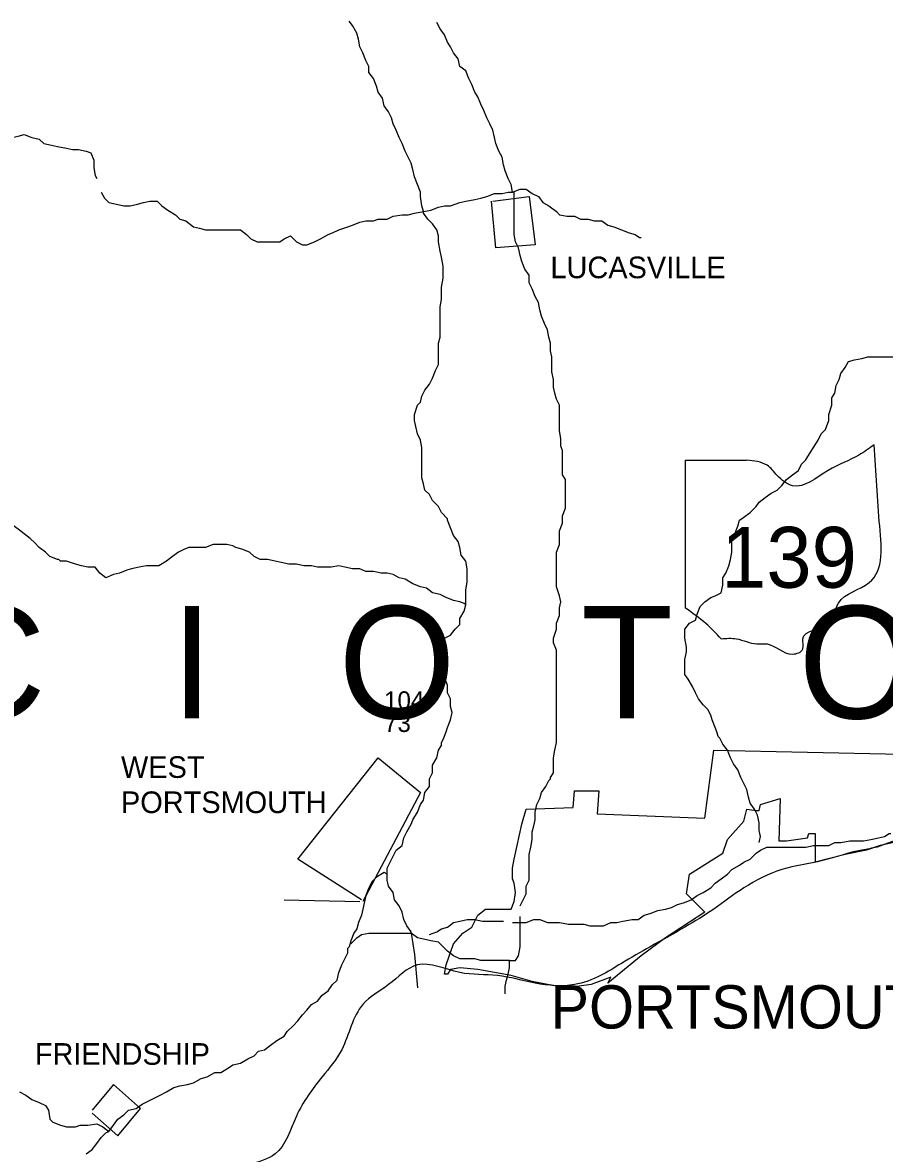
# Model space of a CAD drawing. Extents: x 0 to 40.2, y 0 to 22.
# Drawn here: x 5.589 to 6.366, y 16.218 to 17.238 of the extents above; entities that cross this region are included whole.
import ezdxf

# ---------------------------------------------------------------- set-up
doc = ezdxf.new("R2010")
doc.units = 0
doc.layers.add('Default', color=7, linetype='Continuous')
doc.layers.add('TR_Turning_Path1', color=7, linetype='Continuous')

msp = doc.modelspace()

# ---------------------------------------------------------------- linework, layer by layer
at = {"layer": 'Default'}
msp.add_line((5.8248, 16.4467), (5.893, 16.4454), dxfattribs=at)
for points in [[(5.9448, 17.0916), (5.9421, 17.0984), (5.9407, 17.1052), (5.9393, 17.1107), (5.9366, 17.1162), (5.9339, 17.1216), (5.9312, 17.1284), (5.9284, 17.1339), (5.9257, 17.1407), (5.923, 17.1462), (5.9216, 17.1516), (5.9189, 17.1571), (5.9148, 17.1625), (5.9134, 17.1693), (5.9094, 17.1748), (5.908, 17.1802), (5.9053, 17.1871), (5.9012, 17.1925), (5.9012, 17.198), (5.8984, 17.2034), (5.8957, 17.2102), (5.893, 17.2157), (5.8916, 17.2225), (5.8903, 17.228), (5.8862, 17.2348), (5.8834, 17.2389)], [(6.0307, 17.0848), (6.0293, 17.0916), (6.0266, 17.0971), (6.0239, 17.1039), (6.0225, 17.1093), (6.0212, 17.1162), (6.0184, 17.1216), (6.0157, 17.1284), (6.0143, 17.1339), (6.013, 17.1407), (6.0102, 17.1462), (6.0075, 17.1516), (6.0048, 17.1584), (6.0021, 17.1639), (5.9993, 17.1707), (5.9966, 17.1748), (5.9939, 17.1816), (5.9912, 17.1871), (5.9884, 17.1939), (5.983, 17.198), (5.9816, 17.2048), (5.9775, 17.2102), (5.9748, 17.2157), (5.9721, 17.2198), (5.9693, 17.2266), (5.9653, 17.232), (5.9625, 17.2375)], [(5.5603, 17.1325), (5.5658, 17.1325), (5.5726, 17.1325), (5.5794, 17.1339), (5.5849, 17.1352), (5.5903, 17.1366), (5.5971, 17.1339), (5.6039, 17.1325), (5.608, 17.1284), (5.6149, 17.1271), (5.6203, 17.1257), (5.6285, 17.1243), (5.6339, 17.123), (5.6394, 17.123), (5.6462, 17.1216), (5.6503, 17.1202), (5.653, 17.1134), (5.653, 17.1066), (5.6544, 17.0998), (5.6558, 17.0971), (5.6558, 17.0971)], [(5.6598, 17.0848), (5.6626, 17.0793), (5.6667, 17.0753), (5.6735, 17.0739), (5.6803, 17.0725), (5.6858, 17.0725), (5.6926, 17.0739), (5.698, 17.0753), (5.7035, 17.0766), (5.7103, 17.0766), (5.7144, 17.0725), (5.7198, 17.0684), (5.7267, 17.0643), (5.7307, 17.0603), (5.7362, 17.0589), (5.743, 17.0534), (5.7485, 17.0521), (5.7539, 17.0507), (5.7607, 17.0507), (5.7676, 17.0507), (5.773, 17.0507), (5.7785, 17.0507), (5.7853, 17.0507), (5.7907, 17.0466), (5.7948, 17.0425), (5.8003, 17.0398), (5.8071, 17.0398)], [(5.9503, 17.0671), (5.9489, 17.0725), (5.9475, 17.0807), (5.9475, 17.0848), (5.9448, 17.0916), (5.9448, 17.0916)], [(5.9503, 17.0671), (5.9571, 17.0684), (5.9639, 17.0712), (5.9693, 17.0725), (5.9748, 17.0725), (5.983, 17.0753), (5.9884, 17.0766), (5.9966, 17.078), (6.0021, 17.0793), (6.0075, 17.0807), (6.0143, 17.0834), (6.0212, 17.0834), (6.0266, 17.0848), (6.0307, 17.0848)], [(6.0307, 17.0848), (6.0375, 17.0875), (6.043, 17.0875), (6.0484, 17.0834), (6.0539, 17.0807), (6.058, 17.0753), (6.0634, 17.0725), (6.0702, 17.0671), (6.073, 17.0643), (6.0798, 17.063), (6.0866, 17.063), (6.092, 17.0603), (6.0989, 17.0603), (6.1043, 17.0589), (6.1111, 17.0589), (6.1166, 17.0548), (6.122, 17.0534), (6.1289, 17.0507), (6.1357, 17.048), (6.1411, 17.0466), (6.1452, 17.0439), (6.1466, 17.0439)], [(6.073, 16.8857), (6.073, 16.8926), (6.0702, 16.898), (6.0689, 16.9035), (6.0675, 16.9089), (6.0675, 16.9157), (6.0661, 16.9226), (6.0661, 16.9294), (6.0661, 16.9362), (6.0648, 16.9416), (6.0648, 16.9485), (6.0634, 16.9539), (6.0621, 16.9607), (6.0593, 16.9662), (6.0566, 16.973), (6.0552, 16.9785), (6.0539, 16.9853), (6.0511, 16.9907), (6.0484, 16.9975), (6.0457, 17.003), (6.0457, 17.0098), (6.0416, 17.0153), (6.0389, 17.0221), (6.0375, 17.0275), (6.0361, 17.0344), (6.0334, 17.0398), (6.0321, 17.0466), (6.0321, 17.0507), (6.0321, 17.0589), (6.0321, 17.0643), (6.0321, 17.0712), (6.0321, 17.078), (6.0321, 17.0834), (6.0321, 17.0848), (6.0307, 17.0848)], [(6.013, 17.0766), (6.0457, 17.0807), (6.0511, 17.0371), (6.0157, 17.0344), (6.0116, 17.0766)], [(5.8071, 17.0398), (5.8125, 17.0398), (5.8207, 17.0398), (5.8248, 17.0425), (5.8303, 17.0453), (5.8357, 17.0398), (5.8412, 17.0371), (5.8453, 17.0371), (5.8521, 17.0398), (5.8575, 17.0425), (5.8644, 17.0466), (5.8684, 17.048), (5.8739, 17.0507), (5.8821, 17.0534), (5.8862, 17.0548), (5.893, 17.0575), (5.8984, 17.0589), (5.9053, 17.0589), (5.9094, 17.0603), (5.9175, 17.0603), (5.923, 17.063), (5.9312, 17.0643), (5.9366, 17.0643), (5.9421, 17.0657), (5.9503, 17.0671), (5.9503, 17.0671)], [(5.9475, 16.8953), (5.9489, 16.9007), (5.9516, 16.9062), (5.9557, 16.9116), (5.9584, 16.9171), (5.9612, 16.9239), (5.9639, 16.9294), (5.9639, 16.9362), (5.9639, 16.9416), (5.9639, 16.9485), (5.9653, 16.9539), (5.9653, 16.9607), (5.9653, 16.9675), (5.9653, 16.9744), (5.9653, 16.9812), (5.9666, 16.988), (5.9666, 16.9934), (5.9666, 16.9989), (5.968, 17.0071), (5.968, 17.0139), (5.968, 17.018), (5.9666, 17.0262), (5.9653, 17.0316), (5.9639, 17.0398), (5.9639, 17.0453), (5.9625, 17.0507), (5.9584, 17.0562), (5.9543, 17.0603), (5.9503, 17.0657), (5.9503, 17.0671), (5.9503, 17.0671)], [(6.3157, 16.8789), (6.3157, 16.8844), (6.3184, 16.8926), (6.3184, 16.8994), (6.3211, 16.9035), (6.3225, 16.9103), (6.3252, 16.9157), (6.3266, 16.9212), (6.3306, 16.9266), (6.3334, 16.9321), (6.3388, 16.9335), (6.3456, 16.9348), (6.3511, 16.9362), (6.3579, 16.9362), (6.3647, 16.9362), (6.3702, 16.9362), (6.3756, 16.9362), (6.3825, 16.9335), (6.3865, 16.9307), (6.392, 16.9294), (6.392, 16.9294)], [(5.9721, 16.7903), (5.9666, 16.7958), (5.9639, 16.8012), (5.9584, 16.8067), (5.9557, 16.8121), (5.9516, 16.8162), (5.9503, 16.8217), (5.9489, 16.8271), (5.9489, 16.8353), (5.9489, 16.8421), (5.9489, 16.8476), (5.9489, 16.8544), (5.9475, 16.8612), (5.9448, 16.8667), (5.9434, 16.8735), (5.9421, 16.8789), (5.9421, 16.8844), (5.9448, 16.8926), (5.9475, 16.8953)], [(6.0702, 16.7289), (6.0702, 16.7358), (6.0702, 16.7412), (6.0702, 16.748), (6.0702, 16.7535), (6.0702, 16.7603), (6.073, 16.7671), (6.073, 16.7726), (6.073, 16.7794), (6.0757, 16.7862), (6.0757, 16.793), (6.0784, 16.7998), (6.0784, 16.8053), (6.0784, 16.8108), (6.0784, 16.8189), (6.0784, 16.8257), (6.0757, 16.8298), (6.0757, 16.838), (6.0757, 16.8435), (6.0757, 16.8517), (6.0743, 16.8557), (6.0743, 16.8626), (6.073, 16.8694), (6.073, 16.8762), (6.073, 16.883), (6.073, 16.8844), (6.073, 16.8857)], [(6.2311, 16.7767), (6.2338, 16.7835), (6.2352, 16.7889), (6.2393, 16.7917), (6.2448, 16.7958), (6.2502, 16.8012), (6.2529, 16.8053), (6.2584, 16.8094), (6.2638, 16.8135), (6.2693, 16.8162), (6.2734, 16.8203), (6.2775, 16.8257), (6.2829, 16.8298), (6.2884, 16.8339), (6.2911, 16.8394), (6.2952, 16.8435), (6.2993, 16.8503), (6.302, 16.8544), (6.3061, 16.8612), (6.3088, 16.8667), (6.3129, 16.8707), (6.3157, 16.8789), (6.3157, 16.8789)], [(6.3613, 16.7879), (6.3567, 16.8569)], [(6.1865, 16.7097), (6.1865, 16.8431), (6.2417, 16.8431)], [(5.623, 16.7521), (5.6217, 16.7535), (5.6203, 16.7535), (5.6135, 16.7562), (5.6094, 16.7603), (5.6039, 16.7644), (5.5999, 16.7685), (5.5958, 16.7726), (5.5903, 16.7767), (5.5849, 16.7808), (5.5794, 16.7848), (5.574, 16.7889), (5.5699, 16.7903), (5.563, 16.7944), (5.5576, 16.7958), (5.5521, 16.7985), (5.5467, 16.8026)], [(5.9884, 16.7126), (5.9884, 16.7194), (5.9884, 16.7262), (5.9898, 16.733), (5.9898, 16.7399), (5.9898, 16.7453), (5.9884, 16.7521), (5.9843, 16.7576), (5.983, 16.7644), (5.9816, 16.7698), (5.9775, 16.7753), (5.9748, 16.7821), (5.9721, 16.7889), (5.9721, 16.7889), (5.9721, 16.7903)], [(5.7812, 16.7644), (5.7812, 16.7644), (5.7785, 16.7658), (5.773, 16.7671), (5.7662, 16.7671), (5.7607, 16.7671), (5.7539, 16.7644), (5.7457, 16.7644), (5.7389, 16.7644), (5.7348, 16.763), (5.7294, 16.7603), (5.7239, 16.7562), (5.7185, 16.7521), (5.7117, 16.748), (5.7062, 16.748), (5.7007, 16.748), (5.6939, 16.7467), (5.6871, 16.7453), (5.683, 16.7439), (5.6762, 16.7412), (5.6708, 16.7399), (5.6639, 16.7371), (5.6585, 16.7412), (5.6544, 16.7467), (5.6476, 16.7467), (5.6421, 16.748), (5.6367, 16.7494), (5.6285, 16.7521), (5.623, 16.7521)], [(6.1861, 16.6908), (6.1902, 16.6962), (6.1957, 16.699), (6.197, 16.7044), (6.1998, 16.7112), (6.2039, 16.7153), (6.2093, 16.7194), (6.2134, 16.7208), (6.2188, 16.7235), (6.2202, 16.7303), (6.2202, 16.7371), (6.2229, 16.7412), (6.2257, 16.748), (6.227, 16.7535), (6.2284, 16.7603), (6.2284, 16.7644), (6.2284, 16.7726), (6.2311, 16.7753), (6.2311, 16.7767)], [(5.9884, 16.7126), (5.9871, 16.7139), (5.983, 16.7153), (5.9775, 16.7167), (5.9707, 16.7194), (5.9653, 16.7221), (5.9584, 16.7235), (5.953, 16.7276), (5.9475, 16.7289), (5.9407, 16.7317), (5.9339, 16.7358), (5.9284, 16.7371), (5.923, 16.7399), (5.9175, 16.7412), (5.9121, 16.7412), (5.9053, 16.7426), (5.8984, 16.7426), (5.893, 16.7453), (5.8862, 16.7453), (5.8794, 16.7467), (5.8739, 16.748), (5.8671, 16.7467), (5.8603, 16.7467), (5.8548, 16.7467), (5.8494, 16.748), (5.8425, 16.748), (5.8357, 16.7494), (5.8289, 16.7494), (5.8221, 16.7508), (5.8166, 16.7521), (5.8098, 16.7535), (5.803, 16.7535), (5.7976, 16.7562), (5.7935, 16.7603), (5.7866, 16.763), (5.7812, 16.7644)], [(6.0648, 16.5572), (6.0675, 16.5612), (6.0675, 16.5681), (6.0675, 16.5749), (6.0689, 16.5817), (6.0702, 16.5885), (6.0702, 16.594), (6.0702, 16.6008), (6.0702, 16.6062), (6.0702, 16.6131), (6.0702, 16.6199), (6.0702, 16.6253), (6.0702, 16.6335), (6.0702, 16.639), (6.0702, 16.6458), (6.0702, 16.6499), (6.0702, 16.658), (6.0702, 16.6635), (6.0702, 16.6717), (6.0675, 16.6785), (6.0675, 16.6826), (6.0702, 16.6908), (6.0702, 16.6962), (6.073, 16.703), (6.073, 16.7099), (6.0743, 16.7153), (6.073, 16.7208), (6.0702, 16.7289)], [(5.9666, 16.5858), (5.9666, 16.5885), (5.968, 16.5912), (5.9707, 16.5981), (5.9721, 16.6021), (5.9748, 16.609), (5.9762, 16.6158), (5.9748, 16.6212), (5.9748, 16.6281), (5.9721, 16.6335), (5.9721, 16.6403), (5.9693, 16.6471), (5.968, 16.6526), (5.9666, 16.658), (5.9653, 16.6649), (5.9653, 16.6717), (5.9653, 16.6785), (5.9693, 16.6826), (5.9748, 16.6853), (5.9789, 16.6908), (5.983, 16.6949), (5.983, 16.7003), (5.9871, 16.7071), (5.9884, 16.7126)], [(5.9666, 16.5858), (5.9666, 16.5885), (5.968, 16.5912), (5.9707, 16.5981), (5.9721, 16.6021), (5.9748, 16.609), (5.9762, 16.6158), (5.9748, 16.6212), (5.9748, 16.6281), (5.9721, 16.6335), (5.9721, 16.6403), (5.9693, 16.6471), (5.968, 16.6526), (5.9666, 16.658), (5.9653, 16.6649), (5.9653, 16.6717), (5.9653, 16.6785), (5.9693, 16.6826), (5.9748, 16.6853), (5.9789, 16.6908), (5.983, 16.6949), (5.983, 16.7003), (5.9871, 16.7071), (5.9884, 16.7126)], [(6.2148, 16.5981), (6.2134, 16.6021), (6.2107, 16.609), (6.2093, 16.6131), (6.2066, 16.6185), (6.2025, 16.6226), (6.1984, 16.6281), (6.1957, 16.6335), (6.1929, 16.639), (6.1889, 16.6458), (6.1861, 16.6499), (6.1861, 16.6567), (6.1861, 16.6635), (6.1875, 16.6703), (6.1875, 16.6744), (6.1861, 16.6826), (6.1861, 16.688), (6.1861, 16.6908)], [(6.2529, 16.4985), (6.2543, 16.504), (6.2529, 16.5094), (6.2529, 16.5163), (6.2516, 16.5231), (6.2488, 16.5285), (6.2448, 16.534), (6.2434, 16.5394), (6.242, 16.5462), (6.2393, 16.5517), (6.2366, 16.5572), (6.2338, 16.564), (6.2298, 16.5694), (6.227, 16.5749), (6.2243, 16.5817), (6.2202, 16.5871), (6.2175, 16.5926), (6.2161, 16.594), (6.2148, 16.5981)], [(5.9175, 16.4699), (5.9175, 16.4713), (5.9175, 16.4753), (5.9203, 16.4808), (5.923, 16.4863), (5.9257, 16.4917), (5.9312, 16.4958), (5.9325, 16.5026), (5.9353, 16.5081), (5.9393, 16.5149), (5.9407, 16.519), (5.9448, 16.5258), (5.9475, 16.5326), (5.9503, 16.5367), (5.9516, 16.5435), (5.9557, 16.549), (5.9557, 16.5558), (5.9584, 16.5612), (5.9584, 16.5681), (5.9625, 16.5749), (5.9639, 16.5817), (5.9666, 16.5858)], [(5.9175, 16.4699), (5.9175, 16.4713), (5.9175, 16.4753), (5.9203, 16.4808), (5.923, 16.4863), (5.9257, 16.4917), (5.9312, 16.4958), (5.9325, 16.5026), (5.9353, 16.5081), (5.9393, 16.5149), (5.9407, 16.519), (5.9448, 16.5258), (5.9475, 16.5326), (5.9503, 16.5367), (5.9516, 16.5435), (5.9557, 16.549), (5.9557, 16.5558), (5.9584, 16.5612), (5.9584, 16.5681), (5.9625, 16.5749), (5.9639, 16.5817), (5.9666, 16.5858)], [(5.8944, 16.4467), (5.8371, 16.4835), (5.9094, 16.5749), (5.9475, 16.5435), (5.8957, 16.4454)], [(5.9707, 16.3881), (5.9775, 16.4072), (5.9857, 16.4167), (5.9939, 16.4222), (5.9993, 16.4331), (6.0062, 16.4385), (6.0293, 16.4385), (6.0321, 16.4454), (6.0334, 16.4535), (6.0321, 16.4617), (6.0307, 16.4658), (6.0307, 16.4753), (6.0321, 16.4835), (6.0348, 16.4958), (6.0389, 16.5149), (6.043, 16.5285), (6.0852, 16.5299), (6.0866, 16.5449), (6.1084, 16.5449), (6.107, 16.5244), (6.2039, 16.5203), (6.212, 16.5817), (6.4656, 16.5762)], [(6.0457, 16.4685), (6.0457, 16.4753), (6.0457, 16.4822), (6.0457, 16.4876), (6.0471, 16.4944), (6.0484, 16.5013), (6.0484, 16.5081), (6.0498, 16.5135), (6.0511, 16.519), (6.0511, 16.5258), (6.0525, 16.5326), (6.0552, 16.5381), (6.0566, 16.5435), (6.0607, 16.549), (6.0634, 16.5544), (6.0648, 16.5558), (6.0648, 16.5572)], [(6.2039, 16.4358), (6.1875, 16.4522), (6.1902, 16.4699), (6.2202, 16.489), (6.2243, 16.5013), (6.2393, 16.5176), (6.242, 16.5285), (6.2502, 16.5272), (6.2529, 16.5272), (6.2543, 16.5326), (6.272, 16.5381), (6.2707, 16.4999), (6.2775, 16.4999), (6.2966, 16.5026), (6.2979, 16.5067), (6.3034, 16.5067), (6.3034, 16.4808)], [(6.2829, 16.4944), (6.2884, 16.4944), (6.2952, 16.4944), (6.302, 16.4958), (6.3088, 16.4958), (6.3157, 16.4958), (6.3211, 16.4985), (6.3266, 16.4985), (6.3347, 16.4999), (6.3402, 16.4999), (6.347, 16.4999), (6.3538, 16.5013), (6.3606, 16.5026), (6.3661, 16.504), (6.3702, 16.5067), (6.3716, 16.5067)], [(6.3934, 16.5026), (6.362, 16.4958), (6.3497, 16.4917), (6.3306, 16.4876), (6.3034, 16.4808)], [(6.1616, 16.4372), (6.1684, 16.4385), (6.1739, 16.4399), (6.1793, 16.4426), (6.1848, 16.444), (6.1916, 16.4467), (6.197, 16.4508), (6.2025, 16.4535), (6.2093, 16.4576), (6.2134, 16.4617), (6.2188, 16.4658), (6.2243, 16.4699), (6.2284, 16.474), (6.2352, 16.4781), (6.2393, 16.4808), (6.2448, 16.4835), (6.2502, 16.489), (6.2543, 16.4917), (6.2598, 16.4944), (6.2598, 16.4944)], [(6.2598, 16.4944), (6.2666, 16.4944), (6.2734, 16.4944), (6.2802, 16.4944), (6.2829, 16.4944)], [(5.9175, 16.4699), (5.9175, 16.4699), (5.9148, 16.4713), (5.908, 16.4672), (5.9039, 16.4631), (5.9012, 16.4576), (5.8984, 16.4508), (5.8971, 16.4454), (5.8957, 16.4385), (5.8944, 16.4331), (5.8916, 16.4263), (5.8903, 16.4208)], [(5.9393, 16.4167), (5.9393, 16.4181), (5.9353, 16.4235), (5.9325, 16.429), (5.9312, 16.4358), (5.9284, 16.4413), (5.9243, 16.4467), (5.923, 16.4535), (5.9189, 16.459), (5.9175, 16.4644), (5.9175, 16.4699)], [(5.9393, 16.4167), (5.9393, 16.4181), (5.9353, 16.4235), (5.9325, 16.429), (5.9312, 16.4358), (5.9284, 16.4413), (5.9243, 16.4467), (5.923, 16.4535), (5.9189, 16.459), (5.9175, 16.4644), (5.9175, 16.4699)], [(6.0375, 16.4413), (6.0402, 16.4467), (6.043, 16.4522), (6.043, 16.459), (6.0457, 16.4644), (6.0457, 16.4685)], [(6.2039, 16.4358), (6.1684, 16.4126), (6.1466, 16.3963), (6.1166, 16.3717), (6.1193, 16.3772), (6.1016, 16.3704), (6.0798, 16.3676), (6.0621, 16.3704), (6.0484, 16.3731), (6.0293, 16.3785), (5.9993, 16.384), (5.983, 16.3854), (5.9748, 16.384), (5.9721, 16.3799)], [(6.0375, 16.4263), (6.0375, 16.4317)], [(6.1248, 16.4263), (6.1302, 16.4276), (6.1384, 16.429), (6.1439, 16.429), (6.1493, 16.4331), (6.1548, 16.4344), (6.1616, 16.4372)], [(5.8903, 16.4208), (5.8875, 16.4167), (5.8848, 16.4099), (5.8834, 16.4045)], [(5.9557, 16.4154), (5.9625, 16.4181), (5.9666, 16.4208), (5.9721, 16.4222), (5.9775, 16.4263), (5.983, 16.4276), (5.9898, 16.429), (5.9966, 16.429), (6.0034, 16.4276), (6.0089, 16.4276), (6.0157, 16.4276), (6.0212, 16.4276), (6.0225, 16.4276)], [(6.028, 16.3922), (6.0334, 16.3922), (6.0361, 16.3963), (6.0375, 16.4045), (6.0375, 16.4099), (6.0375, 16.4167), (6.0375, 16.4222), (6.0375, 16.4263)], [(6.0307, 16.4263), (6.0375, 16.4263), (6.0375, 16.4263)], [(6.0375, 16.4263), (6.043, 16.4263), (6.0498, 16.429), (6.0552, 16.429), (6.0621, 16.4263), (6.0675, 16.4263), (6.073, 16.4263), (6.0811, 16.4249), (6.0866, 16.4249), (6.0948, 16.4249), (6.1002, 16.4235), (6.107, 16.4235), (6.1125, 16.4235), (6.1193, 16.4263), (6.122, 16.4263), (6.1248, 16.4263)], [(5.8848, 16.4072), (5.8903, 16.4126), (5.8944, 16.4154), (5.9012, 16.4167), (5.908, 16.4167), (5.9148, 16.4167), (5.9189, 16.4167), (5.9257, 16.4167), (5.9325, 16.4167), (5.9393, 16.4167), (5.9393, 16.4167)], [(6.028, 16.3922), (6.0266, 16.3922), (6.0225, 16.3922), (6.0157, 16.3922), (6.0089, 16.3922), (6.0021, 16.3922), (5.9966, 16.3935), (5.9898, 16.3935), (5.983, 16.3935), (5.9775, 16.3963), (5.9721, 16.4004), (5.968, 16.4045), (5.9639, 16.4085), (5.9571, 16.4099), (5.9503, 16.4113), (5.9448, 16.4126), (5.9393, 16.4167)], [(6.028, 16.3922), (6.0266, 16.3922), (6.0225, 16.3922), (6.0157, 16.3922), (6.0089, 16.3922), (6.0021, 16.3922), (5.9966, 16.3935), (5.9898, 16.3935), (5.983, 16.3935), (5.9775, 16.3963), (5.9721, 16.4004), (5.968, 16.4045), (5.9639, 16.4085), (5.9571, 16.4099), (5.9503, 16.4113), (5.9448, 16.4126), (5.9393, 16.4167)], [(5.9393, 16.4167), (5.9421, 16.3976), (5.9448, 16.3676)], [(5.7785, 16.2981), (5.7853, 16.2995), (5.7921, 16.3036), (5.7976, 16.3063), (5.8016, 16.3104), (5.8071, 16.3117), (5.8125, 16.3158), (5.818, 16.3199), (5.8248, 16.324), (5.8275, 16.3281), (5.833, 16.3336), (5.8371, 16.3376), (5.8412, 16.3431), (5.8453, 16.3472), (5.8494, 16.3526), (5.8548, 16.3554), (5.8589, 16.3608), (5.8644, 16.3649), (5.8684, 16.3704), (5.8725, 16.3745), (5.8739, 16.3813), (5.8766, 16.3881), (5.8794, 16.3935), (5.8821, 16.399), (5.8821, 16.4031), (5.8834, 16.4045)], [(6.0266, 16.3799), (6.028, 16.3854), (6.028, 16.3922)], [(5.9721, 16.3799), (5.9693, 16.3799), (5.9707, 16.3881)], [(6.0239, 16.3622), (6.0239, 16.369), (6.0252, 16.3745), (6.0266, 16.3799), (6.0266, 16.3799)], [(5.6667, 16.2381), (5.6708, 16.2436), (5.6748, 16.249), (5.6803, 16.2531), (5.6844, 16.2572), (5.6912, 16.2586), (5.6967, 16.2627), (5.7021, 16.2654), (5.7076, 16.2681), (5.713, 16.2708), (5.7185, 16.2736), (5.7253, 16.2777), (5.7307, 16.279), (5.7376, 16.2804), (5.743, 16.2817), (5.7498, 16.2858), (5.7553, 16.2872), (5.7621, 16.2913), (5.7676, 16.2913), (5.7744, 16.2954), (5.7785, 16.2981), (5.7785, 16.2981)], [(5.6517, 16.2545), (5.6748, 16.234), (5.6953, 16.2586), (5.6708, 16.2804), (5.6517, 16.2572)], [(5.5862, 16.2736), (5.5917, 16.2708), (5.5971, 16.2667), (5.6039, 16.264), (5.6094, 16.2613), (5.6121, 16.2572), (5.6135, 16.249), (5.6162, 16.2463), (5.623, 16.2436), (5.6285, 16.2422), (5.6367, 16.2422), (5.6408, 16.2436), (5.6476, 16.2436), (5.6558, 16.2449), (5.6612, 16.2422), (5.6667, 16.2381)], [(5.6462, 16.2177), (5.6517, 16.2218), (5.6558, 16.2272), (5.6598, 16.2327), (5.6639, 16.2368), (5.6667, 16.2381), (5.6667, 16.2381)]]:
    msp.add_lwpolyline(points, dxfattribs=at)
for points in [[(6.3567, 16.8569), (6.3429, 16.8477), (6.3153, 16.8339), (6.2831, 16.8201), (6.2693, 16.8293), (6.2601, 16.8385), (6.2417, 16.8431)], [(6.2187, 16.6821), (6.2325, 16.6821), (6.2509, 16.6775), (6.2601, 16.6775), (6.2831, 16.6683), (6.2923, 16.6729), (6.2923, 16.6821), (6.3153, 16.6959), (6.3245, 16.7143), (6.3521, 16.7327), (6.3613, 16.7879)], [(6.2187, 16.6821), (6.2049, 16.6959), (6.1865, 16.7097)], [(6.6647, 15.66), (6.6347, 15.6791), (6.6101, 15.6982), (6.5788, 15.7227), (6.5583, 15.7596), (6.5447, 15.795), (6.5324, 15.8264), (6.5229, 15.8727), (6.5174, 15.9123), (6.5174, 15.9545), (6.5174, 15.9927), (6.5147, 16.0445), (6.5011, 16.0854), (6.4902, 16.1195), (6.4738, 16.1454), (6.4574, 16.1645), (6.4493, 16.1918), (6.4493, 16.234), (6.4629, 16.2695), (6.4724, 16.3117), (6.4724, 16.3554), (6.4656, 16.3976), (6.4629, 16.4385), (6.4465, 16.4685), (6.4288, 16.4849), (6.4015, 16.4999), (6.3852, 16.5026), (6.3593, 16.4944), (6.3456, 16.4917), (6.3102, 16.4822), (6.2734, 16.474), (6.2393, 16.4576), (6.212, 16.4385), (6.1861, 16.4222), (6.1548, 16.4045), (6.1289, 16.3895), (6.1098, 16.3785), (6.0866, 16.3704), (6.0511, 16.3717), (6.0171, 16.3785), (5.983, 16.3813), (5.9448, 16.3881), (5.9189, 16.3704), (5.8957, 16.3526), (5.8766, 16.3117), (5.8589, 16.2872), (5.8357, 16.2517), (5.8166, 16.2177), (5.7935, 16.2081), (5.7539, 16.1918), (5.7212, 16.1754), (5.6803, 16.1631), (5.653, 16.1481), (5.6162, 16.1318), (5.5944, 16.1018), (5.5821, 16.0772), (5.5685, 16.0418), (5.559, 16.0077), (5.5562, 15.9668), (5.5249, 15.9382), (5.4908, 15.9123), (5.4431, 15.8891), (5.3926, 15.8891), (5.3517, 15.8809), (5.3067, 15.8809), (5.2631, 15.8864), (5.2222, 15.9054), (5.1963, 15.9232), (5.1622, 15.93), (5.1363, 15.9313), (5.1186, 15.915), (5.0845, 15.9041), (5.0613, 15.8864)]]:
    msp.add_spline(points, degree=3, dxfattribs=at)

# ---------------------------------------------------------------- texts
for s, height, p in [('LUCASVILLE', 0.0195, (6.0648, 17.0071)), ('139', 0.05486, (6.2187, 16.7281)), ('104', 0.01625, (5.9148, 16.6185)), ('73', 0.01625, (5.9148, 16.5981)), ('WEST', 0.0195, (5.6776, 16.5567)), ('PORTSMOUTH', 0.0195, (5.6776, 16.525)), ('PORTSMOUTH', 0.039, (6.0648, 16.3308)), ('FRIENDSHIP', 0.0195, (5.5999, 16.2981))]:
    msp.add_text(s, height=height, dxfattribs=at).set_placement(p)
at = {"layer": 'TR_Turning_Path1'}
msp.add_text('S   C   I   O   T   O', height=0.101489, dxfattribs=at).set_placement((5.3081, 16.6103))

doc.saveas('drawing.dxf')
